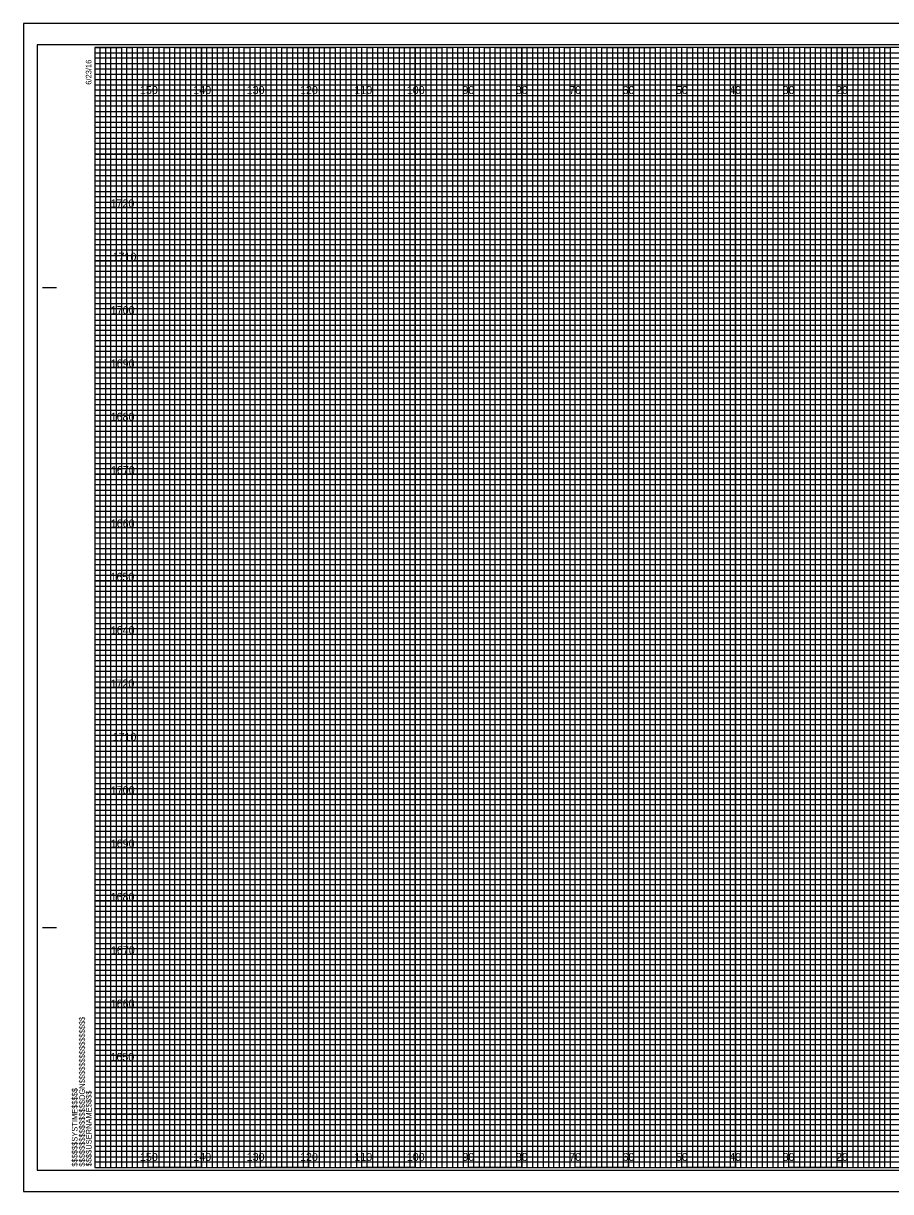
# Model space of a CAD drawing. Extents: x -13 to 323, y -5 to 2414.
# Drawn here: x -13.4 to 149.1, y 215.5 to 434.5 of the extents above; entities that cross this region are included whole.
import ezdxf

# ---------------------------------------------------------------- set-up
doc = ezdxf.new("R2010")
doc.units = 0
for name, color, linetype in [('Prop XS Elevation Labels', 7, 'Continuous'), ('Prop XS Offset Labels', 7, 'Continuous'), ('Sheet Cross Section CELL', 7, 'Continuous'), ('Sheet Cross Section Grid Major CELL', 7, 'Continuous'), ('Sheet Cross Section Grid Middle CELL', 7, 'Continuous'), ('Sheet Cross Section Grid Minor 1 CELL', 7, 'Continuous'), ('Sheet Cross Section Grid Minor 2 CELL', 7, 'Continuous'), ('Sheet Cutting Line CELL', 7, 'Continuous'), ('Sheet DOT Grid CELL', 7, 'Continuous'), ('Sheet Plot Border Inside CELL', 7, 'Continuous'), ('Sheet Plot Border Outside CELL', 7, 'Continuous')]:
    doc.layers.add(name, color=color, linetype=linetype)

msp = doc.modelspace()

# ---------------------------------------------------------------- linework, layer by layer
at = {"layer": 'Sheet Cross Section CELL'}
for p, q in [((-9.8, 385), (-7.3, 385)), ((-9.7, 385), (-7.2, 385)), ((-9.8, 265), (-7.3, 265)), ((-9.7, 265), (-7.2, 265)), ((0, 220), (0, 220)), ((0, 220), (0, 220)), ((0, 220), (0, 220)), ((0, 220), (0, 220)), ((0, 220), (0, 220)), ((0, 220), (0, 220)), ((0, 220), (0, 220))]:
    msp.add_line(p, q, dxfattribs=at)
msp.add_lwpolyline([(320, 430), (0, 430), (0, 220), (320, 220)], close=True, dxfattribs=at)
at = {"layer": 'Sheet Cross Section Grid Major CELL'}
for p, q in [((10, 430), (0, 430)), ((10, 220), (10, 430)), ((30, 430), (20, 430)), ((20, 430), (20, 220)), ((30, 220), (30, 430)), ((50, 430), (40, 430)), ((40, 430), (40, 220)), ((50, 220), (50, 430)), ((70, 430), (60, 430)), ((60, 430), (60, 220)), ((70, 220), (70, 430)), ((90, 430), (80, 430)), ((80, 430), (80, 220)), ((90, 220), (90, 430)), ((110, 430), (100, 430)), ((100, 430), (100, 220)), ((110, 220), (110, 430)), ((130, 430), (120, 430)), ((120, 430), (120, 220)), ((130, 220), (130, 430)), ((150, 430), (140, 430)), ((140, 430), (140, 220)), ((20, 220), (10, 220)), ((40, 220), (30, 220)), ((60, 220), (50, 220)), ((80, 220), (70, 220)), ((100, 220), (90, 220)), ((120, 220), (110, 220)), ((140, 220), (130, 220))]:
    msp.add_line(p, q, dxfattribs=at)
for points in [[(0, 420), (320, 420), (320, 410), (0, 410)], [(0, 400), (320, 400), (320, 390), (0, 390)], [(0, 380), (320, 380), (320, 370), (0, 370)], [(0, 360), (320, 360), (320, 350), (0, 350)], [(0, 340), (320, 340), (320, 330), (0, 330)], [(0, 320), (320, 320), (320, 310), (0, 310)], [(0, 300), (320, 300), (320, 290), (0, 290)], [(0, 280), (320, 280), (320, 270), (0, 270)], [(0, 260), (320, 260), (320, 250), (0, 250)], [(0, 240), (320, 240), (320, 230), (0, 230)]]:
    msp.add_lwpolyline(points, dxfattribs=at)
at = {"layer": 'Sheet Cross Section Grid Middle CELL'}
for points in [[(0, 430), (5, 430), (5, 220), (15, 220), (15, 430), (25, 430), (25, 220), (35, 220), (35, 430), (45, 430), (45, 220), (55, 220), (55, 430), (65, 430), (65, 220), (75, 220), (75, 430), (85, 430), (85, 220), (95, 220), (95, 430), (105, 430), (105, 220), (115, 220), (115, 430), (125, 430), (125, 220), (135, 220), (135, 430), (145, 430), (145, 220), (155, 220)], [(0, 425), (275, 425)], [(0, 405), (320, 405), (320, 415), (0, 415)], [(0, 385), (320, 385), (320, 395), (0, 395)], [(0, 365), (320, 365), (320, 375), (0, 375)], [(0, 345), (320, 345), (320, 355), (0, 355)], [(0, 325), (320, 325), (320, 335), (0, 335)], [(0, 305), (320, 305), (320, 315), (0, 315)], [(0, 285), (320, 285), (320, 295), (0, 295)], [(0, 265), (320, 265), (320, 275), (0, 275)], [(0, 245), (320, 245), (320, 255), (0, 255)], [(0, 225), (320, 225), (320, 235), (0, 235)]]:
    msp.add_lwpolyline(points, dxfattribs=at)
at = {"layer": 'Sheet Cross Section Grid Minor 1 CELL'}
for p, q in [((0, 429), (260, 429)), ((260, 427.98), (0, 427.98)), ((0, 427.98), (0, 427)), ((0, 427), (260, 427)), ((260, 425.89), (0, 425.89)), ((0, 425.89), (0, 424)), ((0, 424), (320, 424))]:
    msp.add_line(p, q, dxfattribs=at)
for points in [[(0, 423), (270, 423), (320, 423), (320, 422), (0, 422)], [(0, 421), (320, 421), (320, 419), (0, 419)], [(0, 418), (320, 418), (320, 417), (0, 416.98)], [(0, 416), (320, 416), (320, 414), (0, 414)], [(0, 413), (320, 413), (320, 412), (0, 412)], [(0, 411), (320, 411), (320, 409), (0, 409)], [(0, 408), (320, 408), (320, 407), (0, 407)], [(0, 406), (320, 406), (320, 404), (0, 404)], [(0, 403), (320, 403), (320, 402), (0, 402)], [(0, 401), (320, 401), (320, 399), (0, 399)], [(0, 398), (320, 398), (320, 397), (0, 397)], [(0, 396), (320, 396), (320, 393.95), (320, 393), (320, 392), (0, 392)], [(0, 394), (320, 394), (320, 393), (0, 393)], [(0, 391), (320, 391), (320, 389), (0, 389.03)], [(0, 389.03), (320, 389), (320, 388), (0, 388)], [(0, 387), (320, 387), (320, 386), (0, 386)], [(0, 384), (320, 384), (320, 383), (0, 383)], [(0, 382), (320, 382), (320, 381), (0, 381)], [(-0.07, 378.89), (320, 378.89), (320, 377.88), (-0.07, 377.88)], [(0, 377), (320, 377), (320, 376), (0, 376)], [(0, 374), (320, 374), (320, 373), (0, 373)], [(0, 372), (320, 372), (320, 371), (0, 371)], [(0, 369), (320, 369), (320, 368), (0, 368)], [(0, 367), (320, 367), (320, 366), (0, 366)], [(0, 364), (320, 364), (320, 363), (0, 363)], [(0, 362), (320, 362), (320, 361), (0, 361)], [(0, 359), (320, 359), (319.99, 357.98), (0, 358)], [(0, 357), (320, 357), (320, 356), (0, 356)], [(0, 354), (320, 354), (320, 353), (0, 353)], [(0, 352), (320, 352), (320, 351), (0, 351)], [(0, 349), (320, 349), (320, 348), (0, 348)], [(0, 347), (320, 347), (320, 346), (0, 346)], [(0, 344), (320, 344), (320, 343), (0, 343)], [(0, 342), (320, 342), (320, 341), (0, 341)], [(0, 339), (320, 339), (320, 338), (0, 338)], [(0, 336.99), (320.07, 336.91), (320, 336), (0, 336)], [(0, 334), (320, 334), (320, 333), (0, 333)], [(0, 332), (320, 332), (320, 331), (0, 331)], [(0, 329), (320, 329), (320, 328), (0, 328)], [(0, 327), (320, 327), (320, 326), (0, 326)], [(0, 324), (320, 324), (320, 323), (0, 323)], [(0, 322), (320, 322), (320, 321), (0, 321)], [(0, 319), (320, 319), (320, 318), (0, 318)], [(0, 317), (320, 317), (320, 316), (0, 316)], [(0, 314), (320, 314), (320, 313), (0, 313)], [(0, 312), (320, 312), (320, 311), (0, 311)], [(0, 309), (320, 309), (320, 308), (0, 308)], [(0, 307), (320, 307), (320, 306), (0, 306)], [(0, 304), (320, 304), (320, 303), (0, 303)], [(0, 302), (320, 302), (320, 301), (0, 301)], [(0, 299), (320, 299), (319.99, 297.98), (0, 298)], [(0, 297), (320, 297), (320, 296), (0, 296)], [(0, 294), (320, 294), (320, 293), (0, 293)], [(0, 292), (320, 292), (320, 291), (0, 291)], [(0, 289), (320, 289), (320, 288), (0, 288)], [(0, 287), (320, 287), (320, 286), (0, 286)], [(0, 284), (320, 284), (320, 283), (0, 283)], [(0, 282), (320, 282), (320, 281), (0, 281)], [(0, 279), (320, 279), (320, 278), (0, 278)], [(0, 276.99), (320.07, 276.91), (320, 276), (0, 276)], [(0, 274), (320, 274), (320, 273), (0, 273)], [(0, 272), (320, 272), (320, 271), (0, 271)], [(0, 269), (320, 269), (320, 268), (0, 268)], [(0, 267), (320, 267), (320, 266), (0, 266)], [(0, 264), (320, 264), (320, 263), (0, 263)], [(0, 262), (320, 262), (320, 261), (0, 261)], [(0, 259), (320, 259), (320, 258), (0, 258)], [(0, 257), (320, 257), (320, 256), (0, 256)], [(0, 254), (320, 254), (320, 253), (0, 253)], [(0, 252), (320, 252), (320, 251), (0, 251)], [(0, 249), (320, 249), (320, 248), (0, 248)], [(0, 247), (320, 247), (320, 246), (0, 246)], [(0, 244), (320, 244), (320, 243), (0, 243)], [(0, 242), (320, 242), (320, 241), (0, 241)], [(0, 239), (320, 239), (320, 238), (0, 238)], [(0, 237), (320, 237), (320, 236), (0, 236)], [(0, 234), (320, 234), (320, 233), (0, 233)], [(0, 232), (320, 232), (320, 231), (0, 231)], [(0, 229), (320, 229), (320, 228), (0, 228)], [(0, 227), (320, 227), (320, 226), (0, 226)], [(0, 224), (320, 224), (320, 223), (0, 223)], [(0, 222), (320, 222), (320, 221), (0, 221)]]:
    msp.add_lwpolyline(points, dxfattribs=at)
at = {"layer": 'Sheet Cross Section Grid Minor 2 CELL'}
for points in [[(0, 220), (1, 220), (1, 430), (2, 430), (2, 220)], [(2, 220), (3, 220), (3, 430), (4, 430), (4, 220)], [(5, 220), (6, 220), (6, 430), (7, 430), (7, 220)], [(7, 220), (8, 220), (8, 430), (9, 430), (9, 220)], [(10, 220), (11, 220), (11, 430), (12, 430), (12, 220)], [(12, 220), (13, 220), (13, 430), (14, 430), (14, 220)], [(15, 220), (16, 220), (16, 430), (17, 430), (17, 220)], [(17, 220), (18, 220), (18, 430), (19, 430), (19, 220)], [(20, 220), (21, 220), (21, 430), (22, 430), (22, 220)], [(22, 220), (23, 220), (23, 430), (24, 430), (24, 220)], [(25, 220), (26, 220), (26, 430), (27, 430), (27, 220)], [(27, 220), (28, 220), (28, 430), (29, 430), (29, 220)], [(30, 220), (31, 220), (31, 430), (32, 430), (32, 220)], [(32, 220), (33, 220), (33, 430), (34, 430), (34, 220)], [(35, 220), (36, 220), (36, 430), (37, 430), (37, 220)], [(37, 220), (38, 220), (38, 430), (39, 430), (39, 220)], [(40, 220), (41, 220), (41, 430), (42, 430), (42, 220)], [(42, 220), (43, 220), (43, 430), (44, 430), (44, 220)], [(45, 220), (46, 220), (46, 430), (47, 430), (47, 220)], [(47, 220), (48, 220), (48, 430), (49, 430), (49, 220)], [(50, 220), (51, 220), (51, 430), (52, 430), (52, 220)], [(52, 220), (53, 220), (53, 430), (54, 430), (54, 220)], [(55, 220), (56, 220), (56, 430), (57, 430), (57, 220)], [(57, 220), (58, 220), (58, 430), (59, 430), (59, 220)], [(60, 220), (61, 220), (61, 430), (62, 430), (62, 220)], [(62, 220), (63, 220), (63, 430), (64, 430), (64, 220)], [(65, 220), (66, 220), (66, 430), (67, 430), (67, 220)], [(67, 220), (68, 220), (68, 430), (69, 430), (69, 220)], [(70, 220), (71, 220), (71, 430), (72, 430), (72, 220)], [(72, 220), (73, 220), (73, 430), (74, 430), (74, 220)], [(75, 220), (76, 220), (76, 430), (77, 430), (77, 220)], [(77, 220), (78, 220), (78, 430), (79, 430), (79, 220)], [(80, 220), (81, 220), (81, 430), (82, 430), (82, 220)], [(82, 220), (83, 220), (83, 430), (84, 430), (84, 220)], [(85, 220), (86, 220), (86, 430), (87, 430), (87, 220)], [(87, 220), (88, 220), (88, 430), (89, 430), (89, 220)], [(90, 220), (91, 220), (91, 430), (92, 430), (92, 220)], [(92, 220), (93, 220), (93, 430), (94, 430), (94, 220)], [(95, 220), (96, 220), (96, 430), (97, 430), (97, 220)], [(97, 220), (98, 220), (98, 430), (99, 430), (99, 220)], [(100, 220), (101, 220), (101, 430), (102, 430), (102, 220)], [(102, 220), (103, 220), (103, 430), (104, 430), (104, 220)], [(105, 220), (106, 220), (106, 430), (107, 430), (107, 220)], [(107, 220), (108, 220), (108, 430), (109, 430), (109, 220)], [(110, 220), (111, 220), (111, 430), (112, 430), (112, 220)], [(112, 220), (113, 220), (113, 430), (114, 430), (114, 220)], [(115, 220), (116, 220), (116, 430), (117, 430), (117, 220)], [(117, 220), (118, 220), (118, 430), (119, 430), (119, 220)], [(120, 220), (121, 220), (121, 430), (122, 430), (122, 220)], [(122, 220), (123, 220), (123, 430), (124, 430), (124, 220)], [(125, 220), (126, 220), (126, 430), (127, 430), (127, 220)], [(127, 220), (128, 220), (128, 430), (129, 430), (129, 220)], [(130, 220), (131, 220), (131, 430), (132, 430), (132, 220)], [(132, 220), (133, 220), (133, 430), (134, 430), (134, 220)], [(135, 220), (136, 220), (136, 430), (137, 430), (137, 220)], [(137, 220), (138, 220), (138, 430), (139, 430), (139, 220)], [(140, 220), (141, 220), (141, 430), (142, 430), (142, 220)], [(142, 220), (143, 220), (143, 430), (144, 430), (144, 220)], [(145, 220), (146, 220), (146, 430), (147, 430), (147, 220)], [(147, 220), (148, 220), (148, 430), (149, 430), (149, 220)]]:
    msp.add_lwpolyline(points, dxfattribs=at)
at = {"layer": 'Sheet Cutting Line CELL'}
for p, q in [((323.3, 434.5), (-13.4, 434.5)), ((-13.4, 434.5), (-13.4, 215.5)), ((-13.4, 215.5), (323.3, 215.5))]:
    msp.add_line(p, q, dxfattribs=at)
at = {"layer": 'Sheet DOT Grid CELL'}
for p, q in [((10, 220), (10, 430)), ((20, 220), (20, 430)), ((30, 220), (30, 430)), ((40, 220), (40, 430)), ((50, 220), (50, 430)), ((60, 220), (60, 430)), ((70, 220), (70, 430)), ((80, 220), (80, 430)), ((90, 220), (90, 430)), ((100, 220), (100, 430)), ((110, 220), (110, 430)), ((120, 220), (120, 430)), ((130, 220), (130, 430)), ((140, 220), (140, 430)), ((0, 420), (320, 420)), ((0, 410), (320, 410)), ((0, 400), (320, 400)), ((0, 390), (320, 390)), ((0, 380), (320, 380)), ((0, 370), (320, 370)), ((0, 360), (320, 360)), ((0, 350), (320, 350)), ((0, 340), (320, 340)), ((0, 330), (320, 330)), ((0, 320), (320, 320)), ((0, 310), (320, 310)), ((0, 300), (320, 300)), ((0, 290), (320, 290)), ((0, 280), (320, 280)), ((0, 270), (320, 270)), ((0, 260), (320, 260)), ((0, 250), (320, 250)), ((0, 240), (320, 240)), ((0, 230), (320, 230))]:
    msp.add_line(p, q, dxfattribs=at)
at = {"layer": 'Sheet Plot Border Inside CELL'}
msp.add_lwpolyline([(-10.8, 219.5), (322.4, 219.5), (322.4, 430.5), (-10.8, 430.5)], close=True, dxfattribs=at)
at = {"layer": 'Sheet Plot Border Outside CELL'}
msp.add_lwpolyline([(-13.4, 215.5), (323.3, 215.5), (323.3, 434.5), (-13.4, 434.5)], close=True, dxfattribs=at)

# ---------------------------------------------------------------- texts
at = {"layer": 'Prop XS Elevation Labels'}
for s, p in [('1720', (2.93, 400)), ('1710', (3.31, 390)), ('1700', (2.98, 380)), ('1690', (2.97, 370)), ('1680', (2.95, 360)), ('1670', (3, 350)), ('1660', (2.97, 340)), ('1650', (2.92, 330)), ('1640', (2.97, 320)), ('1720', (2.93, 310)), ('1710', (3.31, 300)), ('1700', (2.98, 290)), ('1690', (2.97, 280)), ('1680', (2.95, 270)), ('1670', (3, 260)), ('1660', (2.97, 250)), ('1650', (2.92, 240))]:
    msp.add_text(s, height=1.5, dxfattribs=at).set_placement(p)
at = {"layer": 'Prop XS Offset Labels'}
for s, p in [('150', (8.44, 421.25)), ('140', (18.44, 421.25)), ('130', (28.44, 421.25)), ('120', (38.44, 421.25)), ('110', (48.62, 421.25)), ('100', (58.44, 421.25)), ('90', (68.86, 421.25)), ('80', (78.86, 421.25)), ('70', (88.86, 421.25)), ('60', (98.86, 421.25)), ('50', (108.86, 421.25)), ('40', (118.86, 421.25)), ('30', (128.86, 421.25)), ('20', (138.86, 421.25)), ('150', (8.44, 221.25)), ('140', (18.44, 221.25)), ('130', (28.44, 221.25)), ('120', (38.44, 221.25)), ('110', (48.62, 221.25)), ('100', (58.44, 221.25)), ('90', (68.86, 221.25)), ('80', (78.86, 221.25)), ('70', (88.86, 221.25)), ('60', (98.86, 221.25)), ('50', (108.86, 221.25)), ('40', (118.86, 221.25)), ('30', (128.86, 221.25)), ('20', (138.86, 221.25))]:
    msp.add_text(s, height=1.5, dxfattribs=at).set_placement(p)
at = {"layer": 'Sheet Cross Section CELL'}
for s, p in [('6/23/16', (-0.65, 423)), ('$$$$$$$$$$$$$$$$DGN$$$$$$$$$$$$$$$$', (-1.88, 220.18)), ('$$$$$$SYSTIME$$$$$', (-3.26, 220.18)), ('$$$$USERNAME$$$$', (-0.62, 220.23))]:
    msp.add_text(s, height=1.05, rotation=90, dxfattribs=at).set_placement(p)

doc.saveas('drawing.dxf')
